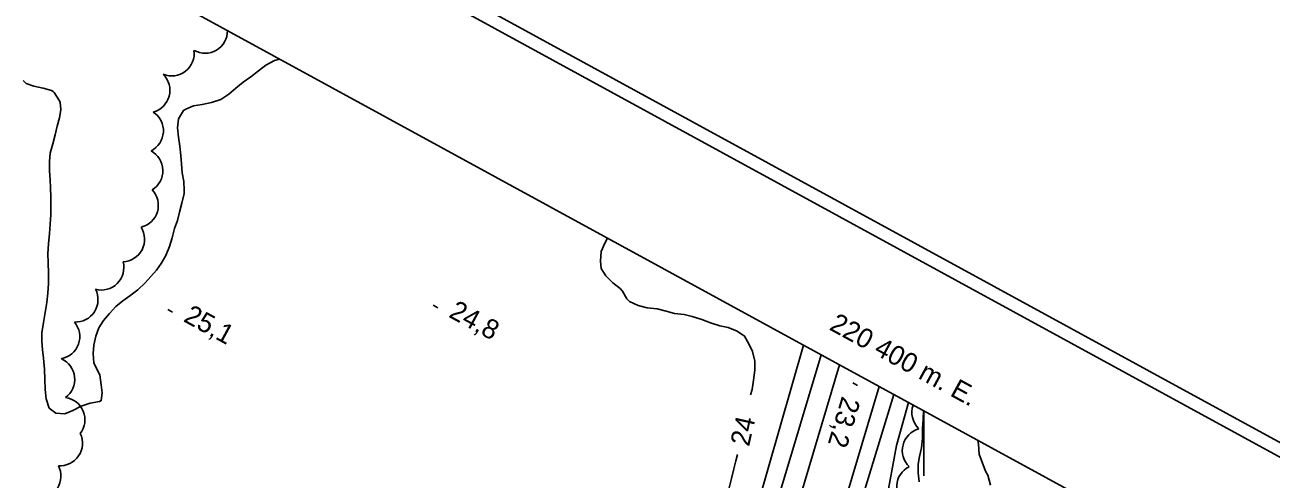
# Model space of a CAD drawing. Extents: x 219136 to 222520, y 5421589 to 5424530.
# Drawn here: x 220261.6 to 220453.5, y 5424265.5 to 5424335.4 of the extents above; entities that cross this region are included whole.
import ezdxf

# ---------------------------------------------------------------- set-up
doc = ezdxf.new("R2010")
doc.units = 0
for name, color, linetype in [('Level 1', 7, 'Continuous'), ('Level 2', 7, 'Continuous'), ('Level 21', 7, 'Continuous'), ('Level 22', 7, 'Continuous'), ('Level 3', 7, 'Continuous'), ('Level 4', 7, 'Continuous'), ('Level 44', 7, 'Continuous'), ('Level 60', 7, 'Continuous'), ('Level 61', 7, 'Continuous')]:
    doc.layers.add(name, color=color, linetype=linetype)

msp = doc.modelspace()

# ---------------------------------------------------------------- linework, layer by layer
at = {"layer": 'Level 1'}
msp.add_lwpolyline([(220408.34, 5424271.43), (220408.42, 5424270.87), (220408.47, 5424270.08), (220408.53, 5424269.31), (220409.51, 5424266.73), (220409.84, 5424266.08), (220410.29, 5424264.56)], dxfattribs=at)
at = {"layer": 'Level 2'}
for points in [[(220286.07, 5424309.46), (220286.09, 5424309.98), (220286.02, 5424311.32), (220285.77, 5424312.67), (220285.68, 5424314.02), (220285.56, 5424315.31), (220285.42, 5424316.78), (220285.21, 5424318.15), (220285.08, 5424319.59), (220285.19, 5424320.96), (220286.01, 5424322.26), (220286.33, 5424322.44), (220287.54, 5424322.99), (220288.86, 5424323.2), (220290.28, 5424323.47), (220291.72, 5424323.93), (220292.99, 5424324.79), (220294.04, 5424325.67), (220295.16, 5424326.62), (220296.33, 5424327.44), (220297.55, 5424328.36), (220298.69, 5424329.22), (220299.99, 5424329.94), (220300.78, 5424330.18)], [(220266.54, 5424319.86), (220266.88, 5424321.14), (220267.08, 5424322.43), (220267, 5424323.47), (220266.87, 5424323.75), (220266.07, 5424325), (220265.91, 5424325.2), (220265.67, 5424325.31), (220264.36, 5424325.67), (220262.94, 5424325.98), (220261.77, 5424326.41), (220261.3, 5424326.87)], [(220286.07, 5424309.46), (220285.71, 5424307.99), (220285.35, 5424306.61), (220285.05, 5424305.33), (220284.6, 5424304.1), (220284.23, 5424302.65), (220283.84, 5424301.33), (220283.24, 5424299.92), (220282.56, 5424298.7), (220281.82, 5424297.67), (220280.97, 5424296.67), (220280.06, 5424295.73), (220278.96, 5424294.63), (220277.73, 5424293.73), (220276.63, 5424292.94), (220275.56, 5424292.06), (220274.59, 5424291.01), (220273.68, 5424289.93), (220272.95, 5424288.77), (220272.48, 5424287.49), (220272.18, 5424286.12), (220272.08, 5424284.83), (220272.19, 5424283.39), (220272.41, 5424282.85), (220273.09, 5424281.55), (220273.32, 5424280.03), (220273.47, 5424278.76), (220273.32, 5424277.58), (220273.04, 5424277.47), (220271.61, 5424277.21), (220270.25, 5424276.71), (220268.96, 5424276.04), (220267.72, 5424275.55), (220266.33, 5424275.65), (220265.32, 5424276.43), (220264.83, 5424277.88), (220264.7, 5424279.3), (220264.65, 5424280.83), (220264.58, 5424282.43), (220264.4, 5424284.1), (220264.28, 5424285.41), (220264.17, 5424286.71), (220264.19, 5424288.01), (220264.41, 5424289.63), (220264.69, 5424291.14), (220264.95, 5424292.67), (220265.11, 5424294.12), (220265.18, 5424295.59), (220265.21, 5424297.15), (220265.15, 5424298.84), (220265.07, 5424300.17), (220265.18, 5424301.74), (220265.34, 5424303.29), (220265.47, 5424304.77), (220265.55, 5424306.2), (220265.54, 5424307.59), (220265.53, 5424308.97), (220265.52, 5424310.33), (220265.43, 5424311.6), (220265.36, 5424312.98), (220265.34, 5424314.4), (220265.47, 5424315.7), (220265.86, 5424317.1), (220266.22, 5424318.49), (220266.54, 5424319.86)], [(220351.3, 5424302.59), (220350.88, 5424301.83), (220350.33, 5424300.56), (220350.19, 5424299.04), (220350.31, 5424297.91), (220351.03, 5424296.79), (220352.09, 5424295.71), (220353.21, 5424294.84), (220353.57, 5424294.45), (220354.27, 5424293.23), (220354.69, 5424292.85), (220356.01, 5424292.23), (220357.38, 5424291.86), (220358.92, 5424291.73), (220360.32, 5424291.34), (220361.62, 5424290.99), (220363.08, 5424290.83), (220364.31, 5424290.55), (220365.79, 5424290.06), (220367.17, 5424289.55), (220368.56, 5424289.11), (220369.89, 5424288.82), (220371.25, 5424288.29), (220372.39, 5424287.52), (220373.07, 5424286.34), (220373.61, 5424285.12), (220373.95, 5424283.66), (220374, 5424282.27), (220373.79, 5424280.71), (220373.55, 5424279.29), (220373.33, 5424278.46)], [(220399.95, 5424276.02), (220399.9, 5424274.71), (220399.81, 5424273.26), (220399.8, 5424271.73), (220399.63, 5424270.29), (220399.34, 5424269), (220399.12, 5424267.77), (220399.13, 5424266.44), (220399.26, 5424265.07)], [(220371.31, 5424269.28), (220371.04, 5424268.32), (220370.74, 5424267.07), (220370.36, 5424265.61), (220370.02, 5424264.13), (220369.78, 5424262.73), (220369.59, 5424261.45), (220369.37, 5424260.08), (220369.27, 5424258.57), (220368.94, 5424257.22), (220368.62, 5424255.65), (220368.27, 5424254.28)]]:
    msp.add_lwpolyline(points, dxfattribs=at)
at = {"layer": 'Level 21'}
for points in [[(220384.21, 5424284.61), (220371.29, 5424241.62), (220352.62, 5424181.41)], [(220350.85, 5424164.5), (220373, 5424236.03), (220386.99, 5424283.1)], [(220393.12, 5424279.75), (220382.1, 5424242.73), (220355.7, 5424156.55)], [(220357.95, 5424153.05), (220373.22, 5424203.77), (220389.8, 5424260.21), (220395.4, 5424278.5)]]:
    msp.add_lwpolyline(points, dxfattribs=at)
at = {"layer": 'Level 22'}
msp.add_lwpolyline([(220397.63, 5424277.28), (220395.78, 5424270.65), (220394.18, 5424262.04), (220392.66, 5424252.57), (220390.86, 5424242.16), (220389.44, 5424232.15), (220388.04, 5424225.25), (220387.38, 5424220.97), (220387.56, 5424218.77)], dxfattribs=at)
at = {"layer": 'Level 3'}
for p, q in [((220283.59, 5424291.59), (220284.29, 5424291.22)), ((220324.44, 5424292.27), (220325.13, 5424291.89)), ((220389.09, 5424280.3), (220389.78, 5424279.92))]:
    msp.add_line(p, q, dxfattribs=at)
at = {"layer": 'Level 4'}
msp.add_lwpolyline([(220381.48, 5424286.1), (220374.3, 5424261.06), (220362.23, 5424219.9), (220352.45, 5424187.98)], dxfattribs=at)
at = {"layer": 'Level 44'}
for centre, start, end in [((220289.3, 5424334.53), 240.6761, 0.6761), ((220284.17, 5424331.03), 247.9082, 7.9082), ((220280.43, 5424325.36), 285.2113, 45.2113), ((220279.43, 5424319.13), 296.6497, 56.6497), ((220279.34, 5424312.98), 301.7011, 61.7011), ((220278.65, 5424307.65), 283.5648, 43.5649), ((220276.54, 5424302.42), 272.4044, 32.4044), ((220273.34, 5424298.07), 254.9152, 14.9152), ((220269.36, 5424293.14), 267.3175, 27.3175), ((220266.55, 5424287.44), 280.2755, 40.2755), ((220265.77, 5424280.86), 306.105, 66.105), ((220267.35, 5424274.63), 322.384, 82.384), ((220401.62, 5424275.74), 160.6464, 225.518), ((220266.97, 5424271.01), 265.671, 25.671), ((220400.15, 5424269.88), 105.518, 225.518), ((220263.65, 5424265.94), 267.7876, 27.7876), ((220399.28, 5424264.32), 116.7633, 236.7633)]:
    msp.add_arc(centre, 3.46, start, end, dxfattribs=at)
at = {"layer": 'Level 60'}
for points in [[(219135.93, 5422982.66), (219981.09, 5424529.89), (222519.95, 5423143.06), (221674.79, 5421595.83), (219135.93, 5422982.66)], [(219138.65, 5422983.46), (219981.9, 5424527.19), (222517.24, 5423142.28), (221673.99, 5421598.55), (219138.65, 5422983.46)]]:
    msp.add_lwpolyline(points, dxfattribs=at)
msp.add_lwpolyline([(219164.83, 5422989.67), (219989.85, 5424500.03), (222033.74, 5423383.57), (221208.72, 5421873.21)], close=True, dxfattribs=at)
at = {"layer": 'Level 61'}
msp.add_line((220400, 5424275.99), (220400, 5424265.99), dxfattribs=at)

# ---------------------------------------------------------------- texts
at = {"layer": 'Level 2'}
msp.add_text('24', height=3, rotation=77.145, dxfattribs=at).set_placement((220373.08, 5424270.41))
at = {"layer": 'Level 3'}
for s, rotation, p in [('25,1', 331.383, (220285.83, 5424289.85)), ('24,8', 331.383, (220326.68, 5424290.53)), ('23,2', 253.4746, (220387.41, 5424278.38))]:
    msp.add_text(s, height=3, rotation=rotation, dxfattribs=at).set_placement(p)
at = {"layer": 'Level 61'}
msp.add_text('220 400 m. E.', height=3, rotation=331.3547, dxfattribs=at).set_placement((220385.29, 5424288.58))

doc.saveas('drawing.dxf')
